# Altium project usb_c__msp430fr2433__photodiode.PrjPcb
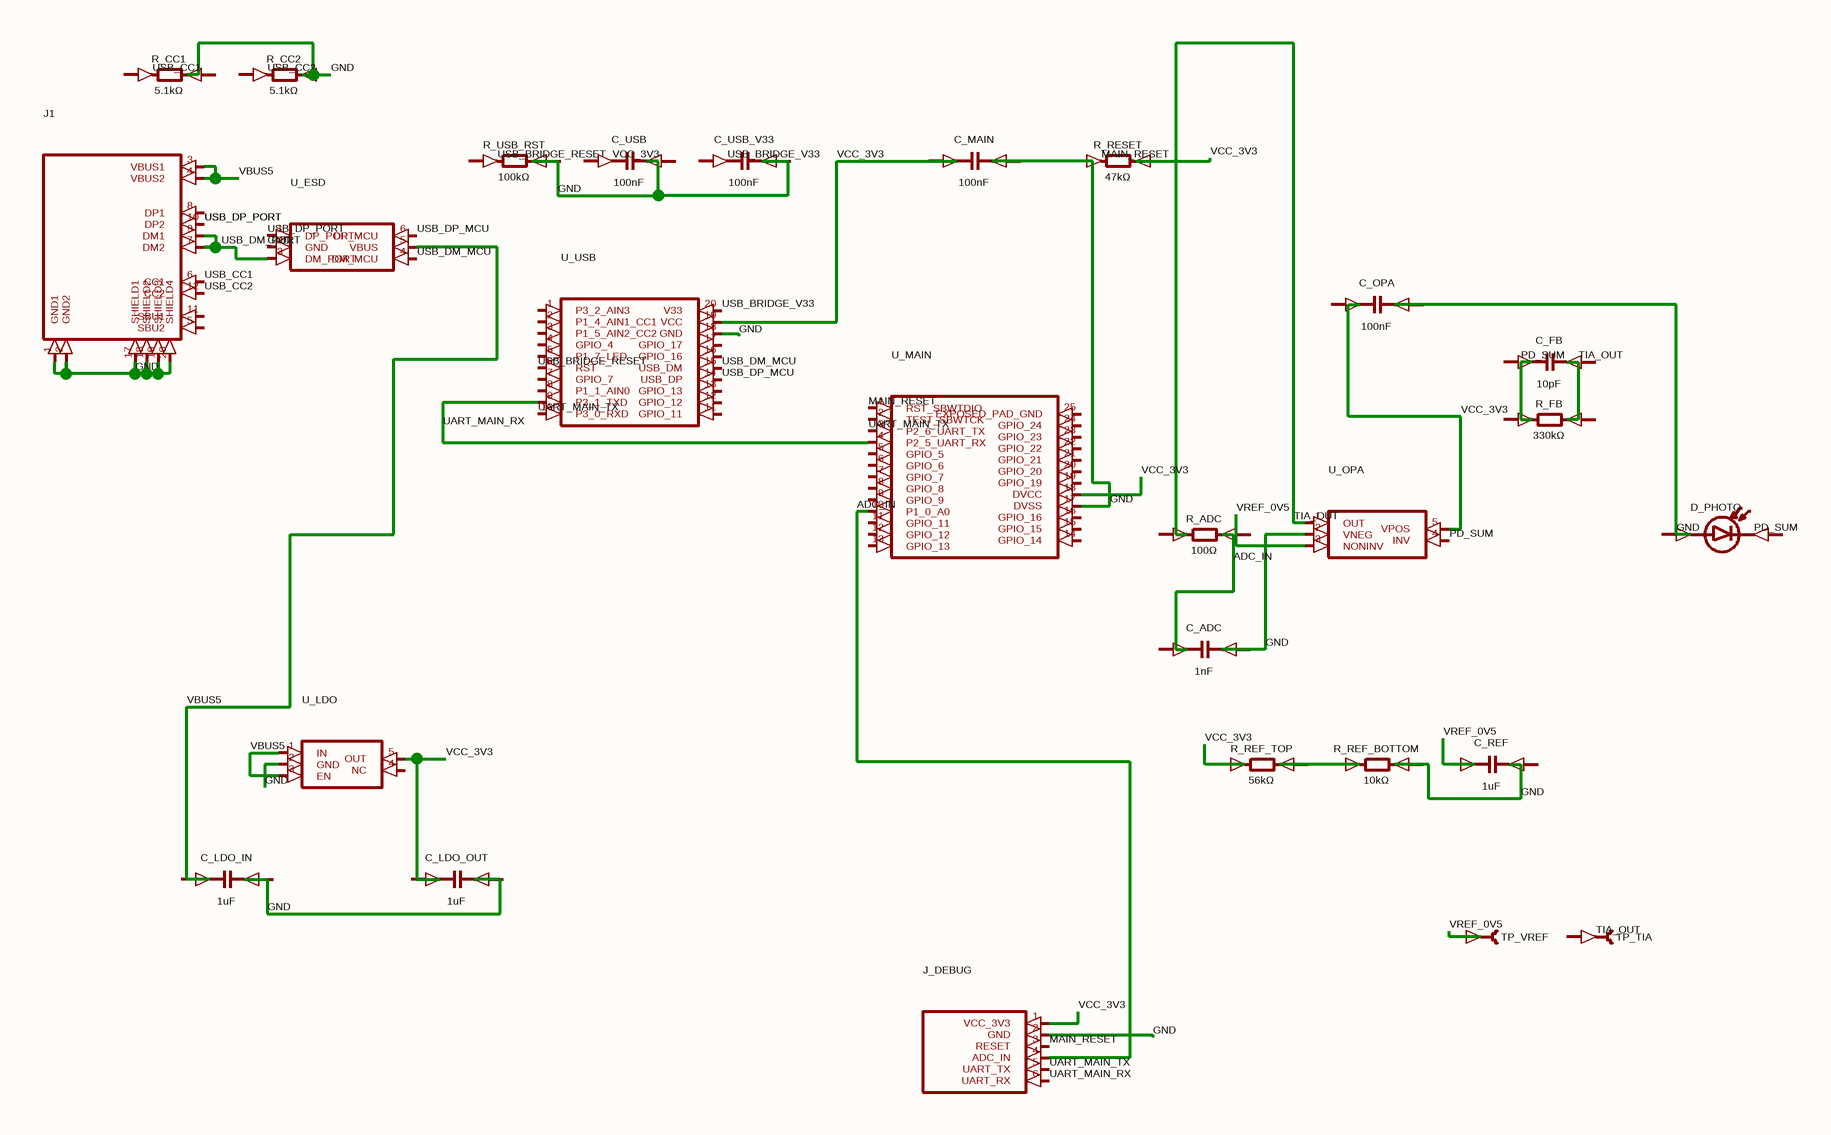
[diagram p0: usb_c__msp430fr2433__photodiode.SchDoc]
1 sheet, 27 parts. Net scope: global (net labels, ports and power ports of the same name join across sheets).
Board file: usb_c__msp430fr2433__photodiode.PcbDoc

## Sheet usb_c__msp430fr2433__photodiode.SchDoc
size 202 x 142 mm

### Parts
C_ADC  1nF
C_FB  10pF
C_LDO_IN  1uF
C_LDO_OUT  1uF
C_MAIN  100nF
C_OPA  100nF
C_REF  1uF
C_USB  100nF
C_USB_V33  100nF
D_PHOTO  (no value)
J1  (no value)
J_DEBUG  (no value)
R_ADC  100Ω
R_CC1  5.1kΩ
R_CC2  5.1kΩ
R_FB  330kΩ
R_REF_BOTTOM  10kΩ
R_REF_TOP  56kΩ
R_RESET  47kΩ
R_USB_RST  100kΩ
TP_TIA  (no value)
TP_VREF  (no value)
U_ESD  (no value)
U_LDO  (no value)
U_MAIN  (no value)
U_OPA  (no value)
U_USB  (no value)

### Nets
ADC_IN: C_ADC.2(neg) C_MAIN.1(pos) C_MAIN.2(neg) C_OPA.2(neg) C_REF.1(pos) J1.1(GND1) J1.2(GND2) J1.17(SHIELD1) J1.18(SHIELD2) J1.19(SHIELD3) J1.20(SHIELD4) J_DEBUG.1(VCC_3V3) J_DEBUG.2(GND) J_DEBUG.4(ADC_IN) R_CC2.2(cathode) R_REF_BOTTOM.2(cathode) R_REF_TOP.1(anode) R_RESET.1(anode) R_RESET.2(cathode) TP_VREF.1(pin1) U_ESD.2(GND) U_LDO.2(GND) U_LDO.5(OUT) U_MAIN.10(P1_0_A0) U_MAIN.17(DVSS) U_MAIN.18(DVCC) U_OPA.2(VNEG) U_OPA.3(NONINV) U_OPA.5(VPOS) U_USB.18(GND) U_USB.19(VCC)  [also labelled GND, VCC_3V3, VREF_0V5]
MAIN_RESET: J_DEBUG.3(RESET) U_MAIN.1(RST_SBWTDIO)
PD_SUM: U_OPA.4(INV)
TIA_OUT: U_OPA.1(OUT)
UART_MAIN_RX: J_DEBUG.6(UART_RX) U_MAIN.4(P2_5_UART_RX) U_USB.9(P3_1_TXD)
UART_MAIN_TX: J_DEBUG.5(UART_TX) U_MAIN.3(P2_6_UART_TX) U_USB.10(P3_0_RXD)
USB_BRIDGE_RESET: U_USB.6(RST)
USB_BRIDGE_V33: U_USB.20(V33)
USB_CC1: J1.6(CC1)
USB_CC2: J1.12(CC2)
USB_DM_MCU: U_ESD.4(DM_MCU) U_USB.15(USB_DM)
USB_DM_PORT: J1.7(DM2) J1.9(DM1) U_ESD.3(DM_PORT)
USB_DP_MCU: U_ESD.6(DP_MCU) U_USB.14(USB_DP)
USB_DP_PORT: J1.10(DP2) U_ESD.1(DP_PORT)
VBUS5: J1.3(VBUS1) J1.4(VBUS2) U_ESD.5(VBUS) U_LDO.1(IN) U_LDO.3(EN)
NetR_REF_BOTTOM_1: R_REF_BOTTOM.1(anode) R_REF_TOP.2(cathode)

Not connected (* = marked no-connect by the designer): C_ADC 1(pos); C_FB 1(pos) 2(neg); C_LDO_IN 1(pos) 2(neg); C_LDO_OUT 1(pos) 2(neg); C_OPA 1(pos); C_REF 2(neg); C_USB 1(pos) 2(neg); C_USB_V33 1(pos) 2(neg); D_PHOTO 1(anode) 2(cathode); J1 5(SBU2) 8(DP1) 11(SBU1); R_ADC 1(anode) 2(cathode); R_CC1 1(anode) 2(cathode); R_CC2 1(anode); R_FB 1(anode) 2(cathode); R_USB_RST 1(anode) 2(cathode); TP_TIA 1(pin1); U_LDO 4(NC); U_MAIN 2(TEST_SBWTCK) 5(GPIO_5) 6(GPIO_6) 7(GPIO_7) 8(GPIO_8) 9(GPIO_9) 11(GPIO_11) 12(GPIO_12) 13(GPIO_13) 14(GPIO_14) 15(GPIO_15) 16(GPIO_16) 19(GPIO_19) 20(GPIO_20) 21(GPIO_21) 22(GPIO_22) 23(GPIO_23) 24(GPIO_24) 25(EXPOSED_PAD_GND); U_USB 1(P3_2_AIN3) 2(P1_4_AIN1_CC1) 3(P1_5_AIN2_CC2) 4(GPIO_4) 5(P1_7_LED) 7(GPIO_7) 8(P1_1_AIN0) 11(GPIO_11) 12(GPIO_12) 13(GPIO_13) 16(GPIO_16) 17(GPIO_17)

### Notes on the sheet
- Labels drawn without touching a wire or pin: MAIN_RESET, PD_SUM, TIA_OUT, USB_BRIDGE_RESET, USB_BRIDGE_V33, USB_CC1, USB_CC2, VCC_3V3

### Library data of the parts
C_ADC C_FB C_LDO_IN C_LDO_OUT C_MAIN C_OPA C_REF C_USB C_USB_V33 = capacitor_right
D_PHOTO = photodiode_horz
J1 = J1
J_DEBUG = J_DEBUG
R_ADC R_CC1 R_CC2 R_FB R_REF_BOTTOM R_REF_TOP R_RESET R_USB_RST = boxresistor_right
TP_TIA TP_VREF = testpoint_right
U_ESD = U_ESD
U_LDO = U_LDO
U_MAIN = U_MAIN
U_OPA = U_OPA
U_USB = U_USB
